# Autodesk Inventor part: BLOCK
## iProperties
Shininess: 64.0
Length Units: 11269
Angle Units: 11279
Time Units: 11290
Mass Units: 11283
Length Display Precision: 3
Angle Display Precision: 2
Compacted: True
Part Number: BLOCK
Document SubType Name: Modeling
Created: 2004-05
Designer: Daniel
Manufacturer: Standard
Standards Organization: Custom
Density: 0.0
Volumn: 0.0
Area: 0.0
PropertySet Name: Model Information
Control State: 0
Master: False
Checked Out: False
Author: Daniel
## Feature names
1. Extrusion1
2. Revolution1
3. Extrusion2
4. Revolution2
5. Circular Pattern1
